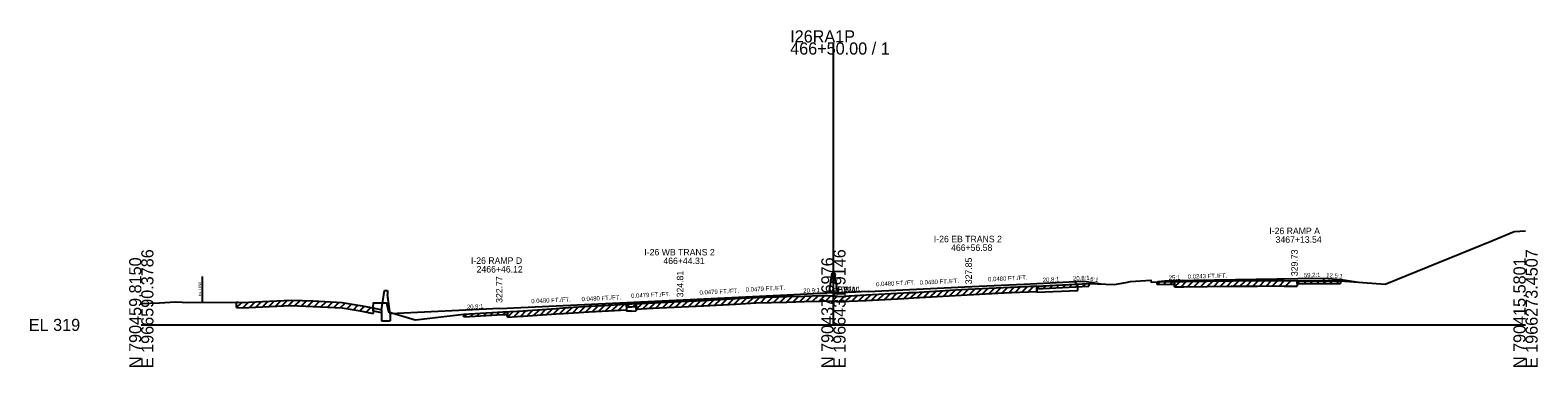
# Model space of a CAD drawing. Extents: x -44 to 4323, y -10 to 9601.
# Drawn here: x 3974.3 to 4322.8, y 4990.3 to 5068.1 of the extents above; entities that cross this region are included whole.
import ezdxf

# ---------------------------------------------------------------- set-up
doc = ezdxf.new("R2010")
doc.units = 0
for name, color, linetype in [('1', 7, 'Continuous'), ('DateStamp', 7, 'Continuous'), ('NotForConst', 7, 'Continuous'), ('QCQA', 7, 'Continuous'), ('RD_SHT_Bndy', 7, 'Continuous'), ('RD_SHT_Iplotshp', 7, 'Continuous'), ('RD_SHT_TX', 7, 'Continuous'), ('RD_XS_ExGround', 7, 'Continuous'), ('RD_XS_ExPaveRet', 7, 'Continuous'), ('RD_XS_MedBWall', 7, 'Continuous'), ('RD_XS_Misc_Line', 7, 'Continuous'), ('RD_XS_Pave', 7, 'Continuous'), ('RD_XS_PaveOvlay', 7, 'Continuous'), ('RD_XS_PaveShd', 7, 'Continuous'), ('RD_XS_TX_Elev_PR', 7, 'Continuous'), ('RD_XS_TX_Profile', 7, 'Continuous'), ('RD_XS_TX_ShdSlope', 7, 'Continuous'), ('RD_XS_TX_Slope', 7, 'Continuous'), ('seal', 7, 'Continuous'), ('TR SN EXTRUDED PANEL SIGNS - GROUND MOUNTED', 7, 'Continuous')]:
    doc.layers.add(name, color=color, linetype=linetype)

msp = doc.modelspace()

# ---------------------------------------------------------------- linework, layer by layer
at = {"layer": 'DateStamp'}
msp.add_lwpolyline([(4000, 5004.96), (4004.24, 5005.13), (4007.9, 5005.32), (4010.99, 5005.21), (4022.01, 5005.26), (4022.39, 5005.26), (4023.32, 5005.21), (4028.02, 5005.4), (4034.61, 5005.74), (4039.7, 5005.53), (4046.4, 5005.17), (4050.61, 5004.49), (4053.57, 5003.91), (4053.7, 5005.12), (4055.01, 5005.12), (4056.7, 5005.12), (4057.17, 5003.03), (4063.32, 5001.15), (4064.06, 5001.23), (4074.57, 5002.46), (4081.03, 5002.84), (4083.61, 5002.99), (4086.86, 5003.19), (4088.25, 5003.26), (4094.81, 5003.72), (4095.88, 5003.8), (4097.61, 5003.91), (4103.49, 5004.3), (4108.04, 5004.53), (4113.43, 5004.84), (4117.95, 5005.1), (4118.32, 5005.12), (4119.8, 5005.2), (4129.97, 5005.67), (4137.4, 5006.07), (4142.05, 5006.32), (4149.21, 5006.53), (4153.2, 5006.66), (4157.03, 5006.77), (4158.64, 5006.8), (4159.47, 5006.74), (4160, 5006.7), (4161.41, 5006.59), (4163.64, 5006.71), (4167.6, 5006.92), (4176.24, 5007.39), (4177.41, 5007.46), (4178.51, 5007.52), (4189.54, 5008.16), (4200.87, 5008.72), (4201.2, 5008.74), (4208.43, 5009.07), (4219.01, 5009.57), (4224.99, 5009.34), (4227.61, 5009.83), (4228.71, 5010.03), (4233.38, 5010.33), (4233.48, 5009.88), (4234.86, 5009.97), (4238.46, 5010.05), (4240.96, 5010.07), (4251.91, 5010.17), (4252.38, 5010.17), (4256.02, 5010.23), (4258, 5010.23), (4261.4, 5010.25), (4264.16, 5010.24), (4268.23, 5010.22), (4276.37, 5010.22), (4277.2, 5010.22), (4287.57, 5009.39), (4312.19, 5019.46), (4317.34, 5021.59), (4320, 5021.76)], dxfattribs=at)
at = {"layer": 'NotForConst'}
for p, q in [((4194.47, 5007.16), (4195.79, 5008.47)), ((4195.98, 5007.23), (4197.3, 5008.55)), ((4197.49, 5007.3), (4198.81, 5008.62)), ((4199, 5007.38), (4200.32, 5008.69)), ((4200.51, 5007.45), (4201.83, 5008.77)), ((4202.02, 5007.52), (4203.34, 5008.84)), ((4203.53, 5007.6), (4204.85, 5008.91)), ((4205.04, 5007.67), (4206.36, 5008.98)), ((4207.01, 5008.38), (4207.67, 5009.04)), ((4208.52, 5008.45), (4209.18, 5009.11)), ((4210.03, 5008.52), (4210.69, 5009.18)), ((4211.54, 5008.59), (4212.2, 5009.25)), ((4213.05, 5008.66), (4213.71, 5009.32)), ((4214.56, 5008.74), (4215.22, 5009.39)), ((4216.07, 5008.81), (4216.74, 5009.46)), ((4217.59, 5008.88), (4218.25, 5009.53)), ((4234.86, 5009.34), (4235.51, 5009.98)), ((4236.37, 5009.38), (4237.02, 5010.02)), ((4237.88, 5009.41), (4238.53, 5010.05)), ((4238.86, 5008.81), (4240.13, 5010.07)), ((4240.37, 5008.82), (4241.64, 5010.08)), ((4241.88, 5008.83), (4243.15, 5010.09)), ((4243.39, 5008.84), (4244.66, 5010.11)), ((4244.9, 5008.86), (4246.17, 5010.12)), ((4246.41, 5008.87), (4247.68, 5010.13)), ((4247.92, 5008.88), (4249.19, 5010.15)), ((4249.43, 5008.9), (4250.7, 5010.16)), ((4250.94, 5008.91), (4252.21, 5010.17)), ((4252.45, 5008.92), (4253.73, 5010.19)), ((4253.96, 5008.95), (4255.24, 5010.21)), ((4255.48, 5008.97), (4256.74, 5010.23)), ((4256.99, 5008.98), (4258.25, 5010.23)), ((4258.5, 5008.98), (4259.76, 5010.24)), ((4260.01, 5008.99), (4261.27, 5010.25)), ((4261.52, 5009), (4262.77, 5010.24)), ((4263.03, 5008.99), (4264.28, 5010.24)), ((4264.54, 5008.99), (4265.79, 5010.23)), ((4267.2, 5009.6), (4267.82, 5010.22)), ((4268.71, 5009.59), (4269.34, 5010.22)), ((4270.22, 5009.59), (4270.85, 5010.22)), ((4271.73, 5009.59), (4272.36, 5010.22)), ((4273.24, 5009.6), (4273.87, 5010.22)), ((4274.75, 5009.6), (4275.38, 5010.22)), ((4276.26, 5009.6), (4276.89, 5010.22)), ((4022.01, 5004.01), (4023.21, 5005.21)), ((4023.51, 5003.97), (4024.81, 5005.27)), ((4025.01, 5004.03), (4026.31, 5005.33)), ((4026.51, 5004.09), (4027.81, 5005.39)), ((4028.01, 5004.15), (4029.33, 5005.47)), ((4029.51, 5004.23), (4030.83, 5005.55)), ((4031.01, 5004.31), (4032.33, 5005.62)), ((4032.51, 5004.38), (4033.83, 5005.7)), ((4034.01, 5004.46), (4035.27, 5005.71)), ((4035.51, 5004.45), (4036.71, 5005.65)), ((4037.01, 5004.39), (4038.21, 5005.59)), ((4038.51, 5004.33), (4039.71, 5005.53)), ((4040.01, 5004.26), (4041.2, 5005.45)), ((4041.51, 5004.18), (4042.7, 5005.37)), ((4043.01, 5004.1), (4044.2, 5005.29)), ((4044.51, 5004.02), (4045.7, 5005.2)), ((4046.01, 5003.94), (4047.13, 5005.05)), ((4114.42, 5003.65), (4115.75, 5004.97)), ((4115.93, 5003.73), (4117.26, 5005.06)), ((4117.44, 5003.82), (4118.77, 5005.14)), ((4118.95, 5003.9), (4120.27, 5005.22)), ((4120.46, 5003.98), (4121.78, 5005.29)), ((4121.97, 5004.05), (4123.29, 5005.36)), ((4123.48, 5004.12), (4124.8, 5005.43)), ((4124.99, 5004.19), (4126.31, 5005.5)), ((4126.5, 5004.26), (4127.82, 5005.57)), ((4128.01, 5004.33), (4129.33, 5005.64)), ((4129.52, 5004.4), (4130.85, 5005.72)), ((4131.03, 5004.48), (4132.36, 5005.8)), ((4132.54, 5004.56), (4133.87, 5005.88)), ((4134.05, 5004.64), (4135.38, 5005.96)), ((4135.56, 5004.72), (4136.89, 5006.04)), ((4137.07, 5004.8), (4138.4, 5006.12)), ((4138.58, 5004.88), (4139.91, 5006.2)), ((4140.09, 5004.96), (4141.42, 5006.28)), ((4141.6, 5005.04), (4142.91, 5006.34)), ((4143.11, 5005.1), (4144.41, 5006.39)), ((4144.62, 5005.14), (4145.92, 5006.43)), ((4146.13, 5005.19), (4147.43, 5006.48)), ((4147.65, 5005.24), (4148.94, 5006.52)), ((4149.16, 5005.28), (4150.45, 5006.57)), ((4150.67, 5005.33), (4151.97, 5006.62)), ((4152.18, 5005.37), (4153.48, 5006.66)), ((4153.69, 5005.42), (4154.98, 5006.71)), ((4155.2, 5005.46), (4156.49, 5006.75)), ((4156.71, 5005.51), (4158, 5006.79)), ((4158.22, 5005.54), (4159.43, 5006.74)), ((4159.73, 5005.47), (4160.9, 5006.63)), ((4161.24, 5005.36), (4162.54, 5006.65)), ((4162.75, 5005.41), (4164.08, 5006.73)), ((4164.26, 5005.49), (4165.59, 5006.81)), ((4165.77, 5005.57), (4167.1, 5006.9)), ((4167.28, 5005.66), (4168.61, 5006.98)), ((4168.79, 5005.74), (4170.12, 5007.06)), ((4170.3, 5005.82), (4171.63, 5007.14)), ((4171.81, 5005.9), (4173.14, 5007.22)), ((4173.32, 5005.98), (4174.65, 5007.31)), ((4174.83, 5006.07), (4176.17, 5007.39)), ((4176.34, 5006.15), (4177.68, 5007.48)), ((4177.85, 5006.24), (4179.19, 5007.56)), ((4179.36, 5006.32), (4180.7, 5007.65)), ((4180.88, 5006.41), (4182.21, 5007.74)), ((4182.39, 5006.5), (4183.72, 5007.83)), ((4183.9, 5006.59), (4185.23, 5007.91)), ((4185.41, 5006.67), (4186.74, 5008)), ((4186.92, 5006.76), (4188.25, 5008.09)), ((4188.43, 5006.85), (4189.76, 5008.17)), ((4189.94, 5006.93), (4191.26, 5008.25)), ((4191.45, 5007.01), (4192.77, 5008.32)), ((4192.96, 5007.08), (4194.28, 5008.4)), ((4047.51, 5003.74), (4048.59, 5004.81)), ((4049.02, 5003.49), (4050.09, 5004.57)), ((4050.52, 5003.25), (4051.56, 5004.3)), ((4052.02, 5002.96), (4053.06, 5004.01)), ((4074.57, 5001.83), (4075.24, 5002.5)), ((4076.08, 5001.92), (4076.75, 5002.59)), ((4077.59, 5002.01), (4078.26, 5002.68)), ((4079.1, 5002.1), (4079.77, 5002.77)), ((4080.61, 5002.19), (4081.28, 5002.86)), ((4082.12, 5002.28), (4082.79, 5002.95)), ((4083.63, 5002.37), (4084.3, 5003.04)), ((4084.64, 5001.81), (4085.98, 5003.13)), ((4086.15, 5001.89), (4087.49, 5003.22)), ((4087.66, 5001.98), (4089, 5003.32)), ((4089.17, 5002.08), (4090.52, 5003.42)), ((4090.68, 5002.18), (4092.03, 5003.52)), ((4092.19, 5002.29), (4093.54, 5003.63)), ((4093.7, 5002.39), (4095.06, 5003.73)), ((4095.21, 5002.5), (4096.57, 5003.84)), ((4096.72, 5002.6), (4098.07, 5003.94)), ((4098.23, 5002.7), (4099.58, 5004.04)), ((4099.74, 5002.8), (4101.09, 5004.14)), ((4101.25, 5002.9), (4102.6, 5004.24)), ((4102.76, 5003), (4104.1, 5004.33)), ((4104.28, 5003.09), (4105.6, 5004.41)), ((4105.79, 5003.17), (4107.11, 5004.48)), ((4107.3, 5003.24), (4108.63, 5004.56)), ((4108.81, 5003.33), (4110.14, 5004.65)), ((4110.32, 5003.41), (4111.65, 5004.74)), ((4112.18, 5004.14), (4112.85, 5004.81)), ((4113.69, 5004.23), (4114.36, 5004.89))]:
    msp.add_line(p, q, dxfattribs=at)
at = {"layer": 'QCQA'}
for p, q in [((4189.54, 5008.16), (4200.87, 5008.72)), ((4200.87, 5008.72), (4201.2, 5008.74)), ((4201.2, 5008.74), (4207.01, 5009.01)), ((4238.86, 5010.06), (4240.96, 5010.07)), ((4240.96, 5010.07), (4251.91, 5010.17)), ((4251.91, 5010.17), (4252.38, 5010.17)), ((4252.38, 5010.17), (4256.02, 5010.23)), ((4256.02, 5010.23), (4258, 5010.23)), ((4258, 5010.23), (4261.4, 5010.25)), ((4261.4, 5010.25), (4264.16, 5010.24)), ((4264.16, 5010.24), (4267.2, 5010.22)), ((4267.2, 5010.22), (4273.34, 5010.22)), ((4114.42, 5004.9), (4117.95, 5005.1)), ((4117.95, 5005.1), (4118.32, 5005.12)), ((4118.32, 5005.12), (4119.8, 5005.2)), ((4119.8, 5005.2), (4129.97, 5005.67)), ((4129.97, 5005.67), (4137.4, 5006.07)), ((4137.4, 5006.07), (4142.05, 5006.32)), ((4142.05, 5006.32), (4149.21, 5006.53)), ((4149.21, 5006.53), (4153.2, 5006.66)), ((4153.2, 5006.66), (4157.03, 5006.77)), ((4157.03, 5006.77), (4158.64, 5006.8)), ((4158.64, 5006.8), (4159.47, 5006.74)), ((4159.47, 5006.74), (4160, 5006.7)), ((4160, 5006.7), (4161.41, 5006.59)), ((4161.41, 5006.59), (4163.64, 5006.71)), ((4163.64, 5006.71), (4167.6, 5006.92)), ((4167.6, 5006.92), (4176.24, 5007.39)), ((4176.24, 5007.39), (4177.41, 5007.46)), ((4177.41, 5007.46), (4178.51, 5007.52)), ((4178.51, 5007.52), (4189.54, 5008.16)), ((4114.42, 5004.9), (4112.18, 5004.77)), ((4112.18, 5004.77), (4112.18, 5003.14)), ((4114.42, 5004.9), (4114.42, 5003.25))]:
    msp.add_line(p, q, dxfattribs=at)
msp.add_lwpolyline([(4238.86, 5010.06), (4238.46, 5010.05), (4236.61, 5010.01)], dxfattribs=at)
at = {"layer": 'RD_SHT_Bndy'}
for p, q in [((4160, 5000), (4160, 5065.29)), ((4000, 5000), (4160, 5000)), ((4160, 5000), (4320, 5000))]:
    msp.add_line(p, q, dxfattribs=at)
at = {"layer": 'RD_SHT_Iplotshp'}
for p, q in [((4207.01, 5009.01), (4207.01, 5007.76)), ((4207.01, 5008.38), (4207.01, 5009.01)), ((4207.01, 5008.38), (4208.43, 5008.45)), ((4208.43, 5008.45), (4219.01, 5008.94)), ((4219.01, 5009.57), (4219.01, 5008.94)), ((4234.86, 5009.34), (4234.86, 5009.97)), ((4234.86, 5009.34), (4238.46, 5009.43)), ((4238.46, 5009.43), (4238.86, 5009.43)), ((4238.86, 5008.81), (4238.86, 5010.06)), ((4238.86, 5010.06), (4238.86, 5009.43)), ((4238.86, 5008.81), (4240.96, 5008.82)), ((4240.96, 5008.82), (4251.91, 5008.92)), ((4251.91, 5008.92), (4252.38, 5008.92)), ((4252.38, 5008.92), (4256.02, 5008.98)), ((4256.02, 5008.98), (4258, 5008.98)), ((4258, 5008.98), (4261.4, 5009)), ((4261.4, 5009), (4264.16, 5008.99)), ((4264.16, 5008.99), (4267.2, 5008.97)), ((4267.2, 5010.22), (4267.2, 5008.97)), ((4267.2, 5009.6), (4267.2, 5010.22)), ((4267.2, 5009.6), (4268.23, 5009.59)), ((4268.23, 5009.59), (4276.37, 5009.6)), ((4276.37, 5009.6), (4277.2, 5009.6)), ((4277.2, 5010.22), (4277.2, 5009.6)), ((4022.01, 5004.01), (4022.01, 5005.26)), ((4137.4, 5004.82), (4142.05, 5005.07)), ((4142.05, 5005.07), (4149.21, 5005.28)), ((4149.21, 5005.28), (4153.2, 5005.41)), ((4153.2, 5005.41), (4157.03, 5005.52)), ((4157.03, 5005.52), (4158.64, 5005.55)), ((4158.64, 5005.55), (4159.47, 5005.49)), ((4159.47, 5005.49), (4160, 5005.45)), ((4160, 5005.45), (4161.41, 5005.34)), ((4161.41, 5005.34), (4163.64, 5005.46)), ((4163.64, 5005.46), (4167.6, 5005.67)), ((4167.6, 5005.67), (4176.24, 5006.14)), ((4176.24, 5006.14), (4177.41, 5006.21)), ((4177.41, 5006.21), (4178.51, 5006.27)), ((4178.51, 5006.27), (4189.54, 5006.91)), ((4189.54, 5006.91), (4200.87, 5007.47)), ((4200.87, 5007.47), (4201.2, 5007.49)), ((4201.2, 5007.49), (4207.01, 5007.76)), ((4022.01, 5004.01), (4022.39, 5004.01)), ((4022.39, 5004.01), (4023.32, 5003.96)), ((4023.32, 5003.96), (4028.02, 5004.15)), ((4028.02, 5004.15), (4034.61, 5004.49)), ((4034.61, 5004.49), (4039.7, 5004.28)), ((4039.7, 5004.28), (4046.4, 5003.92)), ((4046.4, 5003.92), (4050.61, 5003.24)), ((4050.61, 5003.24), (4053.57, 5002.66)), ((4053.57, 5003.91), (4053.57, 5002.66)), ((4074.57, 5001.83), (4074.57, 5002.46)), ((4074.57, 5001.83), (4081.03, 5002.22)), ((4081.03, 5002.22), (4083.61, 5002.37)), ((4083.61, 5002.37), (4084.64, 5002.43)), ((4084.64, 5001.81), (4084.64, 5003.06)), ((4084.64, 5003.06), (4084.64, 5002.43)), ((4084.64, 5001.81), (4086.86, 5001.94)), ((4086.86, 5001.94), (4088.25, 5002.01)), ((4088.25, 5002.01), (4094.81, 5002.47)), ((4094.81, 5002.47), (4095.88, 5002.55)), ((4095.88, 5002.55), (4097.61, 5002.66)), ((4097.61, 5002.66), (4103.49, 5003.05)), ((4103.49, 5003.05), (4108.04, 5003.28)), ((4108.04, 5003.28), (4112.18, 5003.52)), ((4112.18, 5004.77), (4112.18, 5003.52)), ((4112.18, 5004.14), (4112.18, 5004.77)), ((4112.18, 5004.14), (4113.43, 5004.21)), ((4113.43, 5004.21), (4114.42, 5004.27)), ((4114.42, 5003.65), (4114.42, 5004.9)), ((4114.42, 5004.9), (4114.42, 5004.27)), ((4114.42, 5003.65), (4117.95, 5003.85)), ((4117.95, 5003.85), (4118.32, 5003.87)), ((4118.32, 5003.87), (4119.8, 5003.95)), ((4119.8, 5003.95), (4129.97, 5004.42)), ((4129.97, 5004.42), (4137.4, 5004.82))]:
    msp.add_line(p, q, dxfattribs=at)
at = {"layer": 'RD_XS_ExPaveRet'}
msp.add_line((4055.55, 5003.52), (4055.55, 5000.93), dxfattribs=at)
at = {"layer": 'RD_XS_Misc_Line'}
for p, q in [((4207.01, 5007.53), (4207.01, 5009.01)), ((4216, 5009.45), (4216, 5010.01)), ((4216, 5009.45), (4216.5, 5009.47)), ((4216.5, 5007.99), (4216.5, 5009.47)), ((4236.61, 5010.01), (4236.61, 5010.1)), ((4273.34, 5010.22), (4273.34, 5010.83)), ((4207.01, 5007.53), (4216.5, 5007.99)), ((4053.57, 5003.24), (4053.57, 5003.91)), ((4053.57, 5003.24), (4055.55, 5002.85)), ((4113.3, 5003.19), (4112.18, 5003.14)), ((4113.3, 5003.19), (4114.42, 5003.25))]:
    msp.add_line(p, q, dxfattribs=at)
at = {"layer": 'RD_XS_Pave'}
for p, q in [((4218, 5010.1), (4221.85, 5009.46)), ((4277.34, 5010.51), (4280.81, 5009.93))]:
    msp.add_line(p, q, dxfattribs=at)
at = {"layer": 'RD_XS_PaveOvlay'}
msp.add_line((4014.05, 5011.22), (4014.05, 5005.22), dxfattribs=at)
at = {"layer": 'RD_XS_PaveShd'}
for p, q in [((4216, 5010.01), (4218, 5010.1)), ((4236.61, 5010.1), (4234.98, 5009.97)), ((4273.34, 5010.83), (4277.34, 5010.51))]:
    msp.add_line(p, q, dxfattribs=at)
at = {"layer": 'RD_XS_TX_Elev_PR'}
for p, q in [((4204, 5009.43), (4216, 5010.01)), ((4240.61, 5010.26), (4236.61, 5010.1)), ((4267.33, 5010.73), (4273.34, 5010.83)), ((4149.3, 5006.96), (4160, 5007.47)), ((4168, 5007.7), (4160, 5007.32)), ((4160, 5007.47), (4160, 5007.32)), ((4053.57, 5003.91), (4055.55, 5003.52)), ((4055.55, 5003.52), (4055.55, 5002.85)), ((4082.87, 5003.77), (4057.55, 5002.56))]:
    msp.add_line(p, q, dxfattribs=at)
at = {"layer": 'RD_XS_TX_ShdSlope'}
for p, q in [((4159, 5007.42), (4159.67, 5011.97)), ((4160.33, 5011.97), (4159.67, 5011.97)), ((4160.33, 5011.82), (4160.33, 5011.97)), ((4161, 5007.37), (4160.33, 5011.82)), ((4055.55, 5003.52), (4056.22, 5007.97)), ((4056.22, 5007.97), (4056.88, 5007.97)), ((4056.88, 5007.97), (4056.88, 5007.01)), ((4057.55, 5002.56), (4056.88, 5007.01)), ((4057.55, 5002.56), (4057.55, 5000.93)), ((4055.55, 5000.93), (4057.55, 5000.93))]:
    msp.add_line(p, q, dxfattribs=at)
at = {"layer": 'RD_XS_TX_Slope'}
for p, q in [((4168, 5007.7), (4192, 5008.85)), ((4192, 5008.85), (4204, 5009.43)), ((4240.61, 5010.26), (4243.29, 5010.32)), ((4243.29, 5010.32), (4267.33, 5010.73)), ((4082.87, 5003.77), (4125.3, 5005.81)), ((4125.3, 5005.81), (4149.3, 5006.96))]:
    msp.add_line(p, q, dxfattribs=at)

# ---------------------------------------------------------------- texts
at = {"layer": '1'}
for s, p in [('I-26 RAMP A', (4260.76, 5020.98)), ('I-26 EB TRANS 2', (4183.22, 5019.1)), ('3467+13.54', (4262.22, 5018.98)), ('I-26 RAMP D', (4076.21, 5014.11)), ('I-26 WB TRANS 2', (4116.29, 5016.06)), ('466+44.31', (4120.69, 5014.06)), ('466+56.58', (4187.2, 5017.1)), ('2466+46.12', (4077.52, 5012.11))]:
    msp.add_text(s, height=1.5, dxfattribs=at).set_placement(p)
at = {"layer": 'RD_SHT_Bndy'}
for s, p in [('I26RA1P', (4150, 5065.29)), ('466+50.00 / 1', (4150, 5062.49)), ('EL 319', (3974, 4998.6))]:
    msp.add_text(s, height=2.8, dxfattribs=at).set_placement(p)
for s, p in [('N 790459.8150', (4000, 4990)), ('E 1966590.3786', (4002.8, 4990)), ('N 790437.6976', (4160, 4990)), ('E 1966431.9146', (4162.8, 4990)), ('N 790415.5801', (4320, 4990)), ('E 1966273.4507', (4322.8, 4990))]:
    msp.add_text(s, height=2.8, rotation=90, dxfattribs=at).set_placement(p)
at = {"layer": 'RD_SHT_TX'}
msp.add_text('325.70', height=1, rotation=90, dxfattribs=at).set_placement((4161, 5006.7))
at = {"layer": 'RD_XS_ExGround'}
for s, rotation, p in [('20.9:1', 2.7437, (4153.06, 5007.39)), ('20.8:1', 2.7481, (4162.41, 5007.68)), ('20.8:1', 2.7481, (4208.41, 5009.89)), ('20.9:1', 2.7436, (4075.28, 5003.66))]:
    msp.add_text(s, height=1, rotation=rotation, dxfattribs=at).set_placement(p)
at = {"layer": 'RD_XS_MedBWall'}
for s, rotation, p in [('12.5:1', 355.4277, (4273.88, 5011.04)), ('20.8:1', 2.7481, (4215.41, 5010.23))]:
    msp.add_text(s, height=1, rotation=rotation, dxfattribs=at).set_placement(p)
at = {"layer": 'RD_XS_PaveOvlay'}
msp.add_text('Ex. R/W ', height=0.65, rotation=90, dxfattribs=at).set_placement((4013.8, 5006.61))
at = {"layer": 'RD_XS_TX_Profile'}
for s, p in [('WBW', (4159, 5007.42)), ('EBW', (4161, 5007.37))]:
    msp.add_text(s, height=1.5, dxfattribs=at).set_placement(p)
at = {"layer": 'seal'}
for s, p in [(' 327.85', (4192, 5008.85)), (' 329.73', (4267.33, 5010.73)), (' 324.81', (4125.3, 5005.81)), ('322.77', (4083.49, 5005.1))]:
    msp.add_text(s, height=1.5, rotation=90, dxfattribs=at).set_placement(p)
at = {"layer": 'TR SN EXTRUDED PANEL SIGNS - GROUND MOUNTED'}
for s, rotation, p in [('0.0243 FT./FT.', 1.3922, (4241.91, 5010.68)), ('59.2:1', 0.9672, (4268.75, 5011)), ('0.0479 FT./FT.', 2.7437, (4139.73, 5007.66)), ('0.0480 FT./FT.', 2.7481, (4169.89, 5008.91)), ('0.0480 FT./FT.', 2.7481, (4179.95, 5009.28)), ('0.0480 FT./FT.', 2.7481, (4195.77, 5010.04)), ('6:1', 350.5377, (4219.3, 5010.17)), ('25:1', 2.2888, (4237.54, 5010.39)), ('0.0480 FT./FT.', 2.75, (4090.17, 5004.98)), ('0.0480 FT./FT.', 2.7458, (4101.8, 5005.47)), ('0.0479 FT./FT.', 2.7436, (4113.25, 5006.23)), ('0.0479 FT./FT.', 2.7437, (4129.07, 5006.99))]:
    msp.add_text(s, height=1, rotation=rotation, dxfattribs=at).set_placement(p)

doc.saveas('drawing.dxf')
